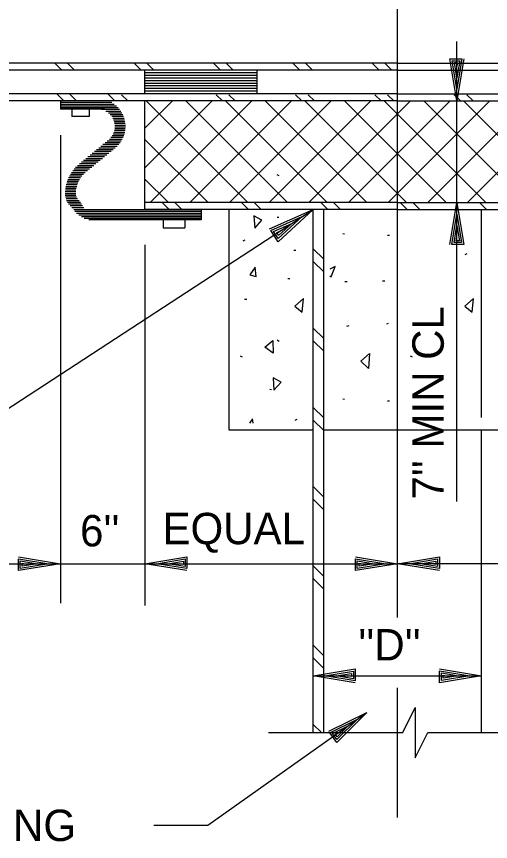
# Model space of a CAD drawing. Extents: x 22422.9 to 22498.9, y 22369.6 to 22415.
# Drawn here: x 22428.867 to 22431.684, y 22387.542 to 22392.447 of the extents above; entities that cross this region are included whole.
import ezdxf

# ---------------------------------------------------------------- set-up
doc = ezdxf.new("R2010")
doc.units = 0
for name, color, linetype in [('Level 1', 7, 'Continuous'), ('Level 10', 7, 'Continuous'), ('Level 2', 7, 'Continuous'), ('Level 4', 7, 'Continuous'), ('Level 44', 7, 'Continuous'), ('Level 7', 7, 'Continuous'), ('Level 8', 7, 'Continuous')]:
    doc.layers.add(name, color=color, linetype=linetype)

msp = doc.modelspace()

# ---------------------------------------------------------------- linework, layer by layer
at = {"layer": 'Level 1'}
for p, q in [((22431.1304, 22388.8739), (22431.1304, 22398.3655)), ((22431.4842, 22391.9456), (22431.4842, 22392.2992)), ((22430.2971, 22392.1123), (22429.6304, 22392.1123)), ((22430.2971, 22392.0967), (22429.6304, 22392.0967)), ((22430.2971, 22392.0811), (22429.6304, 22392.0811)), ((22430.2971, 22392.0654), (22429.6304, 22392.0654)), ((22430.2971, 22392.0498), (22429.6304, 22392.0498)), ((22430.2971, 22392.0342), (22429.6304, 22392.0342)), ((22431.1304, 22391.9873), (22428.1304, 22391.9873)), ((22430.2971, 22392.0186), (22429.6304, 22392.0186)), ((22430.2971, 22392.0029), (22429.6304, 22392.0029)), ((22431.1304, 22391.9873), (22434.1304, 22391.9873)), ((22431.1304, 22391.9456), (22428.1304, 22391.9456)), ((22429.6304, 22391.2998), (22429.6304, 22391.9456)), ((22431.1304, 22391.9456), (22434.1304, 22391.9456)), ((22431.4842, 22391.3415), (22431.4842, 22391.9456)), ((22429.1952, 22391.896), (22429.1952, 22391.853)), ((22429.2988, 22391.896), (22429.2988, 22391.853)), ((22431.4842, 22391.904), (22431.4842, 22391.904)), ((22429.2988, 22391.853), (22429.1952, 22391.853)), ((22429.1282, 22391.7424), (22429.1282, 22388.9583)), ((22431.4842, 22391.654), (22431.4842, 22391.654)), ((22430.6304, 22391.5915), (22430.6304, 22391.5915)), ((22430.5746, 22391.5503), (22430.5746, 22391.5503)), ((22431.4842, 22391.5846), (22431.4842, 22391.5846)), ((22431.1304, 22391.3415), (22429.6304, 22391.3415)), ((22431.1304, 22391.2998), (22429.6304, 22391.2998)), ((22431.1304, 22391.3415), (22432.6304, 22391.3415)), ((22431.1304, 22391.2998), (22432.6304, 22391.2998)), ((22431.4842, 22389.5645), (22431.4842, 22391.3415)), ((22429.7392, 22391.2382), (22429.7392, 22391.1905)), ((22429.8666, 22391.2382), (22429.8666, 22391.1905)), ((22429.7392, 22391.1905), (22429.8666, 22391.1905)), ((22429.6304, 22391.0887), (22429.6304, 22388.946)), ((22428.1304, 22389.1938), (22429.1282, 22389.1938)), ((22429.1282, 22389.1938), (22429.6304, 22389.1938)), ((22429.6304, 22389.1938), (22431.1304, 22389.1938)), ((22429.6304, 22389.1938), (22429.6304, 22389.1938)), ((22429.6997, 22389.1938), (22429.6997, 22389.1938)), ((22431.0611, 22389.1938), (22431.0611, 22389.1938)), ((22432.6304, 22389.1938), (22431.1304, 22389.1938)), ((22431.1304, 22389.1938), (22431.1304, 22389.1938)), ((22431.1304, 22389.1938), (22431.1304, 22389.1938)), ((22431.1997, 22389.1938), (22431.1997, 22389.1938)), ((22430.6304, 22388.5272), (22431.6304, 22388.5272)), ((22431.0611, 22388.5272), (22431.0611, 22388.5272)), ((22431.1304, 22388.5272), (22431.1304, 22388.5272)), ((22431.1304, 22388.5272), (22431.1304, 22388.5272)), ((22431.1997, 22388.5272), (22431.1997, 22388.5272)), ((22431.1304, 22387.6841), (22431.1304, 22388.4548)), ((22430.9495, 22388.3088), (22430.9495, 22388.3088)), ((22430.8929, 22388.2687), (22430.8929, 22388.2687)), ((22430.3644, 22388.1894), (22431.1624, 22388.1894)), ((22431.3119, 22388.1894), (22431.8916, 22388.1894))]:
    msp.add_line(p, q, dxfattribs=at)
msp.add_lwpolyline([(22431.1624, 22388.1894), (22431.2369, 22388.3394), (22431.2369, 22388.0398), (22431.3119, 22388.1894)], dxfattribs=at)
at = {"layer": 'Level 10'}
for p, q in [((22427.6563, 22389.3585), (22430.6304, 22391.2998)), ((22430.6304, 22391.2998), (22430.6304, 22391.2998)), ((22430.5651, 22391.2572), (22430.5651, 22391.2572))]:
    msp.add_line(p, q, dxfattribs=at)
msp.add_lwpolyline([(22430.3701, 22391.1854), (22430.6304, 22391.2998), (22430.4209, 22391.1075), (22430.3775, 22391.1741), (22430.5651, 22391.2572), (22430.4228, 22391.1267), (22430.3949, 22391.1694), (22430.5023, 22391.2162), (22430.4246, 22391.1458), (22430.4132, 22391.1634), (22430.437, 22391.1735)], dxfattribs=at)
at = {"layer": 'Level 2'}
for p, q in [((22431.1304, 22392.1696), (22424.4346, 22392.1696)), ((22431.1304, 22392.1279), (22424.4649, 22392.1279)), ((22429.6304, 22391.9873), (22429.6304, 22392.1279)), ((22430.2971, 22391.9873), (22430.2971, 22392.1279)), ((22431.1304, 22392.1696), (22437.8136, 22392.1696)), ((22431.1304, 22392.1279), (22437.7901, 22392.1279)), ((22429.1291, 22391.9456), (22429.1291, 22391.896)), ((22429.3915, 22391.896), (22429.1291, 22391.896)), ((22429.9649, 22391.2998), (22429.9649, 22391.2382)), ((22430.6304, 22388.1894), (22430.6304, 22391.2998)), ((22430.6929, 22388.1894), (22430.6929, 22391.2998)), ((22431.6304, 22390.0623), (22431.6304, 22391.2998)), ((22429.9649, 22391.2382), (22429.2964, 22391.2382)), ((22431.6304, 22388.1894), (22431.6304, 22389.9873))]:
    msp.add_line(p, q, dxfattribs=at)
for points in [[(22431.5255, 22392.195), (22431.4842, 22391.9456), (22431.4428, 22392.195), (22431.5135, 22392.195), (22431.4842, 22392.015), (22431.4562, 22392.1843), (22431.5015, 22392.1843), (22431.4842, 22392.0816), (22431.4695, 22392.1736), (22431.4882, 22392.1736), (22431.4842, 22392.151)], [(22429.473, 22391.9456), (22429.1304, 22391.9456)], [(22429.4124, 22391.9456), (22429.1304, 22391.9456)], [(22429.4328, 22391.9352), (22429.1304, 22391.9352)], [(22429.4482, 22391.9248), (22429.1304, 22391.9248)], [(22429.4606, 22391.9144), (22429.1304, 22391.9144)], [(22429.4709, 22391.904), (22429.1304, 22391.904)], [(22429.4795, 22391.8936), (22429.3714, 22391.8936)], [(22429.4869, 22391.8831), (22429.3981, 22391.8831)], [(22429.4932, 22391.8727), (22429.4134, 22391.8727)], [(22429.4984, 22391.8623), (22429.4243, 22391.8623)], [(22429.5028, 22391.8519), (22429.4326, 22391.8519)], [(22429.5064, 22391.8415), (22429.439, 22391.8415)], [(22429.5093, 22391.8311), (22429.4439, 22391.8311)], [(22429.5114, 22391.8206), (22429.4475, 22391.8206)], [(22429.5129, 22391.8102), (22429.4498, 22391.8102)], [(22429.5137, 22391.7998), (22429.4511, 22391.7998)], [(22429.5139, 22391.7894), (22429.4514, 22391.7894)], [(22429.5046, 22391.7373), (22429.4358, 22391.7373)], [(22429.5078, 22391.7477), (22429.4414, 22391.7477)], [(22429.5104, 22391.7581), (22429.4457, 22391.7581)], [(22429.5122, 22391.7686), (22429.4487, 22391.7686)], [(22429.5134, 22391.779), (22429.4506, 22391.779)], [(22429.4831, 22391.6956), (22429.3936, 22391.6956)], [(22429.4899, 22391.7061), (22429.4064, 22391.7061)], [(22429.4957, 22391.7165), (22429.4188, 22391.7165)], [(22429.5006, 22391.7269), (22429.4284, 22391.7269)], [(22429.4287, 22391.6436), (22429.3298, 22391.6436)], [(22429.4414, 22391.654), (22429.3426, 22391.654)], [(22429.4542, 22391.6644), (22429.3553, 22391.6644)], [(22429.4655, 22391.6748), (22429.3681, 22391.6748)], [(22429.475, 22391.6852), (22429.3809, 22391.6852)], [(22429.3648, 22391.5915), (22429.266, 22391.5915)], [(22429.3776, 22391.6019), (22429.2788, 22391.6019)], [(22429.3904, 22391.6123), (22429.2915, 22391.6123)], [(22429.4031, 22391.6227), (22429.3043, 22391.6227)], [(22429.4159, 22391.6331), (22429.317, 22391.6331)], [(22429.301, 22391.5394), (22429.2091, 22391.5394)], [(22429.3138, 22391.5498), (22429.2182, 22391.5498)], [(22429.3265, 22391.5602), (22429.2286, 22391.5602)], [(22429.3393, 22391.5706), (22429.2405, 22391.5706)], [(22429.3521, 22391.5811), (22429.2532, 22391.5811)], [(22429.2558, 22391.4977), (22429.1817, 22391.4977)], [(22429.2649, 22391.5081), (22429.1874, 22391.5081)], [(22429.2757, 22391.5186), (22429.1938, 22391.5186)], [(22429.2882, 22391.529), (22429.201, 22391.529)], [(22429.2275, 22391.4456), (22429.1627, 22391.4456)], [(22429.2313, 22391.4561), (22429.1653, 22391.4561)], [(22429.236, 22391.4665), (22429.1686, 22391.4665)], [(22429.2415, 22391.4769), (22429.1724, 22391.4769)], [(22429.2481, 22391.4873), (22429.1767, 22391.4873)], [(22429.2191, 22391.3936), (22429.1566, 22391.3936)], [(22429.2195, 22391.404), (22429.1569, 22391.404)], [(22429.2205, 22391.4144), (22429.1576, 22391.4144)], [(22429.2221, 22391.4248), (22429.1588, 22391.4248)], [(22429.2245, 22391.4352), (22429.1605, 22391.4352)], [(22429.2195, 22391.3831), (22429.1569, 22391.3831)], [(22429.2226, 22391.3727), (22429.1576, 22391.3727)], [(22429.2298, 22391.3623), (22429.1614, 22391.3623)], [(22429.2395, 22391.3519), (22429.164, 22391.3519)], [(22429.2466, 22391.3415), (22429.1698, 22391.3415)], [(22429.253, 22391.3311), (22429.1762, 22391.3311)], [(22429.2588, 22391.3206), (22429.1853, 22391.3206)], [(22429.2678, 22391.3102), (22429.1956, 22391.3102)], [(22429.9637, 22391.2976), (22429.2078, 22391.2976)], [(22431.4428, 22391.0921), (22431.4842, 22391.3415), (22431.5255, 22391.0921), (22431.4548, 22391.0921), (22431.4842, 22391.2721), (22431.5122, 22391.1028), (22431.4668, 22391.1028), (22431.4842, 22391.2055), (22431.4988, 22391.1135), (22431.4802, 22391.1135), (22431.4842, 22391.1361)], [(22429.9637, 22391.2872), (22429.2143, 22391.2872)], [(22429.9637, 22391.2768), (22429.2229, 22391.2768)], [(22429.9637, 22391.2664), (22429.2381, 22391.2664)], [(22429.9637, 22391.2559), (22429.2539, 22391.2559)], [(22429.9637, 22391.2455), (22429.2692, 22391.2455)], [(22428.8788, 22389.2352), (22429.1282, 22389.1938), (22428.8788, 22389.1525), (22428.8788, 22389.2232), (22429.0588, 22389.1938), (22428.8895, 22389.1658), (22428.8895, 22389.2112), (22428.9922, 22389.1938), (22428.9002, 22389.1792), (22428.9002, 22389.1978), (22428.9228, 22389.1938)], [(22429.8797, 22389.1525), (22429.6304, 22389.1938), (22429.8797, 22389.2352), (22429.8797, 22389.1645), (22429.6997, 22389.1938), (22429.8691, 22389.2218), (22429.8691, 22389.1765), (22429.7664, 22389.1938), (22429.8584, 22389.2085), (22429.8584, 22389.1898), (22429.8357, 22389.1938)], [(22430.8811, 22389.2352), (22431.1304, 22389.1938), (22430.8811, 22389.1525), (22430.8811, 22389.2232), (22431.0611, 22389.1938), (22430.8917, 22389.1658), (22430.8917, 22389.2112), (22430.9944, 22389.1938), (22430.9024, 22389.1792), (22430.9024, 22389.1978), (22430.9251, 22389.1938)], [(22431.3797, 22389.1525), (22431.1304, 22389.1938), (22431.3797, 22389.2352), (22431.3797, 22389.1645), (22431.1997, 22389.1938), (22431.3691, 22389.2218), (22431.3691, 22389.1765), (22431.2664, 22389.1938), (22431.3584, 22389.2085), (22431.3584, 22389.1898), (22431.3357, 22389.1938)], [(22430.8797, 22388.4858), (22430.6304, 22388.5272), (22430.8797, 22388.5685), (22430.8797, 22388.4978), (22430.6997, 22388.5272), (22430.8691, 22388.5552), (22430.8691, 22388.5098), (22430.7664, 22388.5272), (22430.8584, 22388.5418), (22430.8584, 22388.5232), (22430.8357, 22388.5272)], [(22431.3811, 22388.5685), (22431.6304, 22388.5272), (22431.3811, 22388.4858), (22431.3811, 22388.5565), (22431.5611, 22388.5272), (22431.3917, 22388.4992), (22431.3917, 22388.5445), (22431.4944, 22388.5272), (22431.4024, 22388.5125), (22431.4024, 22388.5312), (22431.4251, 22388.5272)], [(22429.684, 22387.6401), (22430.0045, 22387.6401), (22430.9495, 22388.3088)], [(22430.7221, 22388.1985), (22430.9495, 22388.3088), (22430.7699, 22388.131), (22430.7291, 22388.1887), (22430.8929, 22388.2687), (22430.7709, 22388.1481), (22430.7447, 22388.1851), (22430.8385, 22388.2302), (22430.7719, 22388.1651), (22430.7611, 22388.1804), (22430.7819, 22388.1902)]]:
    msp.add_lwpolyline(points, dxfattribs=at)
at = {"layer": 'Level 44'}
for p, q in [((22430.4269, 22391.4991), (22430.4157, 22391.5059)), ((22430.4266, 22391.2521), (22430.4166, 22391.2529)), ((22430.8152, 22391.1534), (22430.8052, 22391.1551)), ((22430.2238, 22391.1183), (22430.2118, 22391.1123)), ((22431.0842, 22391.1449), (22431.0707, 22391.1449)), ((22430.5278, 22391.0554), (22430.5143, 22391.0554)), ((22431.5422, 22391.0356), (22431.5302, 22391.0296)), ((22430.4921, 22390.8878), (22430.4786, 22390.8878)), ((22430.8312, 22390.8696), (22430.8177, 22390.8696)), ((22431.0552, 22390.8744), (22431.0424, 22390.8744)), ((22430.2351, 22390.7648), (22430.2216, 22390.7648)), ((22430.8419, 22390.6079), (22430.8284, 22390.6041)), ((22431.0749, 22390.6214), (22431.0652, 22390.6176)), ((22430.4269, 22390.5154), (22430.4157, 22390.5221)), ((22430.2092, 22390.4224), (22430.1984, 22390.4274)), ((22431.2192, 22390.4224), (22431.2084, 22390.4274)), ((22430.3819, 22390.2281), (22430.3719, 22390.2289)), ((22430.8152, 22390.1696), (22430.8052, 22390.1714)), ((22431.0842, 22390.1611), (22431.0707, 22390.1611)), ((22430.5322, 22390.0519), (22430.5202, 22390.0459))]:
    msp.add_line(p, q, dxfattribs=at)
for points in [[(22430.2825, 22391.1882), (22430.3252, 22391.2362), (22430.2775, 22391.2617)], [(22430.2918, 22390.9022), (22430.2848, 22390.9569), (22430.254, 22390.9112)], [(22430.5727, 22390.7706), (22430.5214, 22390.7259), (22430.5639, 22390.6901)], [(22431.5827, 22390.7706), (22431.5314, 22390.7259), (22431.5739, 22390.6901)], [(22430.3914, 22390.4446), (22430.3434, 22390.4809), (22430.3894, 22390.5216)], [(22430.9592, 22390.3544), (22430.9129, 22390.3971), (22430.9642, 22390.4429)], [(22430.3964, 22390.2246), (22430.4392, 22390.2726), (22430.3914, 22390.2981)]]:
    msp.add_lwpolyline(points, close=True, dxfattribs=at)
for points in [[(22430.7281, 22390.9047), (22430.7367, 22390.8989), (22430.7604, 22390.9601), (22430.7281, 22390.9444)], [(22430.2725, 22390.0297), (22430.2692, 22390.0559), (22430.2513, 22390.0292)]]:
    msp.add_lwpolyline(points, dxfattribs=at)
at = {"layer": 'Level 7'}
for p, q in [((22430.1304, 22389.9873), (22430.1304, 22391.2998)), ((22430.6304, 22389.9873), (22430.1304, 22389.9873)), ((22432.1304, 22389.9873), (22430.6929, 22389.9873))]:
    msp.add_line(p, q, dxfattribs=at)
at = {"layer": 'Level 8'}
for p, q in [((22431.4842, 22392.015), (22431.4842, 22392.015)), ((22431.4842, 22391.9456), (22431.4842, 22391.9456)), ((22431.4842, 22391.3415), (22431.4842, 22391.3415)), ((22431.4842, 22391.2721), (22431.4842, 22391.2721)), ((22429.0588, 22389.1938), (22429.0588, 22389.1938)), ((22429.1282, 22389.1938), (22429.1282, 22389.1938)), ((22429.6304, 22389.1938), (22429.6304, 22389.1938)), ((22429.6997, 22389.1938), (22429.6997, 22389.1938)), ((22431.0611, 22389.1938), (22431.0611, 22389.1938)), ((22431.1304, 22389.1938), (22431.1304, 22389.1938)), ((22431.1304, 22389.1938), (22431.1304, 22389.1938)), ((22431.1997, 22389.1938), (22431.1997, 22389.1938)), ((22430.6304, 22388.5272), (22430.6304, 22388.5272)), ((22430.6997, 22388.5272), (22430.6997, 22388.5272)), ((22431.5611, 22388.5272), (22431.5611, 22388.5272)), ((22431.6304, 22388.5272), (22431.6304, 22388.5272))]:
    msp.add_line(p, q, dxfattribs=at)
for points in [[(22429.137, 22392.1279), (22429.0953, 22392.1696)], [(22429.2124, 22392.1279), (22429.1708, 22392.1696)], [(22429.6084, 22392.1279), (22429.5667, 22392.1696)], [(22429.6838, 22392.1279), (22429.6422, 22392.1696)], [(22430.0798, 22392.1279), (22430.0382, 22392.1696)], [(22430.1552, 22392.1279), (22430.1136, 22392.1696)], [(22430.5512, 22392.1279), (22430.5095, 22392.1696)], [(22430.6266, 22392.1279), (22430.585, 22392.1696)], [(22431.0226, 22392.1279), (22430.981, 22392.1696)], [(22431.098, 22392.1279), (22431.0564, 22392.1696)], [(22429.1474, 22391.9456), (22429.1057, 22391.9873)], [(22429.2228, 22391.9456), (22429.1812, 22391.9873)], [(22429.4522, 22391.9456), (22429.4105, 22391.9873)], [(22429.5276, 22391.9456), (22429.4911, 22391.9821)], [(22430.0902, 22391.9456), (22430.0538, 22391.9821)], [(22430.1657, 22391.9456), (22430.1292, 22391.9821)], [(22430.5616, 22391.9456), (22430.5252, 22391.9821)], [(22430.6371, 22391.9456), (22430.6006, 22391.9821)], [(22431.033, 22391.9456), (22430.9966, 22391.9821)], [(22431.1085, 22391.9456), (22431.072, 22391.9821)], [(22431.5044, 22391.9456), (22431.468, 22391.9821)], [(22431.5799, 22391.9456), (22431.5434, 22391.9821)], [(22429.6304, 22391.5467), (22430.0293, 22391.9456)], [(22429.6304, 22391.7824), (22429.7936, 22391.9456)], [(22430.2411, 22391.3415), (22429.6369, 22391.9456)], [(22429.6609, 22391.3415), (22430.265, 22391.9456)], [(22430.4767, 22391.3415), (22429.8726, 22391.9456)], [(22429.8966, 22391.3415), (22430.5007, 22391.9456)], [(22430.7125, 22391.3415), (22430.1083, 22391.9456)], [(22430.1323, 22391.3415), (22430.7365, 22391.9456)], [(22430.9482, 22391.3415), (22430.344, 22391.9456)], [(22430.368, 22391.3415), (22430.9722, 22391.9456)], [(22431.1838, 22391.3415), (22430.5797, 22391.9456)], [(22430.6037, 22391.3415), (22431.2079, 22391.9456)], [(22431.4196, 22391.3415), (22430.8154, 22391.9456)], [(22430.8394, 22391.3415), (22431.4436, 22391.9456)], [(22431.6553, 22391.3415), (22431.0511, 22391.9456)], [(22431.0751, 22391.3415), (22431.6793, 22391.9456)], [(22431.891, 22391.3415), (22431.2868, 22391.9456)], [(22431.3108, 22391.3415), (22431.915, 22391.9456)], [(22432.1267, 22391.3415), (22431.5225, 22391.9456)], [(22431.5465, 22391.3415), (22432.1507, 22391.9456)], [(22430.0054, 22391.3415), (22429.6304, 22391.7164)], [(22429.7697, 22391.3415), (22429.6304, 22391.4807)], [(22429.7748, 22391.2998), (22429.7331, 22391.3415)], [(22429.8502, 22391.2998), (22429.8085, 22391.3415)], [(22430.2462, 22391.2998), (22430.2045, 22391.3415)], [(22430.3216, 22391.2998), (22430.2799, 22391.3415)], [(22430.7176, 22391.2998), (22430.6759, 22391.3415)], [(22430.793, 22391.2998), (22430.7513, 22391.3415)], [(22431.189, 22391.2998), (22431.1473, 22391.3415)], [(22431.2644, 22391.2998), (22431.2227, 22391.3415)], [(22431.6604, 22391.2998), (22431.6187, 22391.3415)], [(22430.6929, 22391.0036), (22430.6304, 22391.0661)], [(22430.6929, 22390.9282), (22430.6304, 22390.9907)], [(22430.6929, 22390.5322), (22430.6304, 22390.5947)], [(22430.6929, 22390.4568), (22430.6304, 22390.5193)], [(22430.6929, 22390.0608), (22430.6304, 22390.1233)], [(22430.6929, 22389.9854), (22430.6304, 22390.0479)], [(22430.6929, 22389.5894), (22430.6304, 22389.6519)], [(22430.6929, 22389.514), (22430.6304, 22389.5765)], [(22430.6929, 22389.118), (22430.6304, 22389.1805)], [(22430.6929, 22389.0426), (22430.6304, 22389.1051)], [(22430.6929, 22388.6466), (22430.6304, 22388.7091)], [(22430.6929, 22388.5712), (22430.6304, 22388.6337)], [(22430.6787, 22388.1894), (22430.6304, 22388.2377)]]:
    msp.add_lwpolyline(points, dxfattribs=at)

# ---------------------------------------------------------------- texts
at = {"layer": 'Level 4'}
msp.add_text("7'' MIN CL ", height=0.186667, rotation=90, dxfattribs=at).set_placement((22431.4058, 22389.5752))
for s, height, p in [("6''", 0.18667, (22429.2448, 22389.2969)), ('EQUAL', 0.18667, (22429.7347, 22389.3096)), ("''D''", 0.18667, (22430.898, 22388.6187)), ('STEEL SHEET PILING', 0.186667, (22426.6406, 22387.5448))]:
    msp.add_text(s, height=height, dxfattribs=at).set_placement(p)

doc.saveas('drawing.dxf')
